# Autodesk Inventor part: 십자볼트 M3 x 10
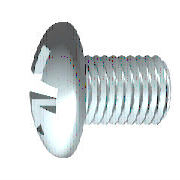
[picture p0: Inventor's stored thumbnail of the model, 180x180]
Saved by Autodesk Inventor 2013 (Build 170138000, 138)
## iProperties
IsCustomPart: 0
Created: 2012-02
Part Number: 십자볼트 M3 x 10
Material: 스테인리스강
Description: 십자 오목 머리 나사
Document SubType Name: Modeling
Standard: KS B 1023
Designer: mduedu
Standards Organization: KS
Language: ko-KR
Size Designation: A  M 3 x 10 - H
Categories: <MemberInstance><Categories><Category DisplayName="조임쇠" InternalName="e4da775c-781d-43d5-af7c-5136215cf5a6" Mnemonic="FSTN"><Category DisplayName="볼트" InternalN
Density: 1 g/cm^3
Author: mduedu
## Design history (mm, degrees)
workplane "Work Plane3"
sketch "스케치2"
  geometry: L1 (-3.72, 0)-(3.72, 0) reference; L2 (0, -3.72)-(0, 3.72) reference; L3 (0, 1.5)-(0, 0); L4 (0, 0)-(1.5, 0); L5 (0, 0)-(1.879, 1.879); L6 (0.253, 1.479)-(0.261, 0.456); L7 (1.479, 0.253)-(0.456, 0.261); L8 (0.253, -1.479)-(0.261, -0.456); L9 (1.479, -0.253)-(0.456, -0.261); L10 (-0.253, 1.479)-(-0.261, 0.456); L11 (-1.479, 0.253)-(-0.456, 0.261); L12 (-1.479, -0.253)-(-0.456, -0.261); L13 (-0.253, -1.479)-(-0.261, -0.456); A1 r 0.45 centre (0, 0) between (0.45, 0) and (0, 0.45); A2 r 1.5 centre (0, 0) between (1.5, 0) and (1.479, 0.253); A3 r 1.5 centre (0, 0) between (0.253, 1.479) and (0, 1.5); A4 r 1.5 centre (0, 0) between (1.479, 0.253) and (0.253, 1.479); A5 r 1.5 centre (0, 0) between (0, -1.5) and (0.253, -1.479); A6 r 1.5 centre (0, 0) between (0.253, -1.479) and (1.479, -0.253); A7 r 1.5 centre (0, 0) between (1.479, -0.253) and (1.5, 0); A8 r 1.5 centre (0, 0) between (-1.479, 0.253) and (-1.5, 0); A9 r 1.5 centre (0, 0) between (-0.253, 1.479) and (-1.479, 0.253); A10 r 1.5 centre (0, 0) between (0, 1.5) and (-0.253, 1.479); A11 r 1.5 centre (0, 0) between (-1.5, 0) and (-1.479, -0.253); A12 r 1.5 centre (0, 0) between (-1.479, -0.253) and (-0.253, -1.479); A13 r 1.5 centre (0, 0) between (-0.253, -1.479) and (0, -1.5); A14 r 0.525 centre (0, 0) between (0.525, 0) and (0, 0.525); A15 r 0.197 centre (0.457, 0.457) between (0.261, 0.456) and (0.456, 0.261); A16 r 0.197 centre (0.457, -0.457) between (0.456, -0.261) and (0.261, -0.456); A17 r 0.197 centre (-0.457, 0.457) between (-0.456, 0.261) and (-0.261, 0.456); A18 r 0.197 centre (-0.457, -0.457) between (-0.261, -0.456) and (-0.456, -0.261); 1 further point
  constraints: 38 point on circle, 22 end point, 19 symmetric about line, 18 centre point, 4 coincident, 3 collinear, 3 point on line, 3 tangent, 1 perpendicular, 21 other
  dimensions: "d4" = 45 deg angle of L5 L4; "d5" = 0.9 diameter of A1 (= 0.3 x SDM); "d6" = 3 diameter of A4 (= SDM); "d7" = 0.2525 distance from line of L6.start L3 (= 0.5 x SBR); "d14" = 1.05 diameter of A14 (= 0.35 x SDM)
extrude "슬롯" join sketch "스케치2" taper "d15" = 5 deg; stored distance "d54" = 10
revolve "절단부" stored, may be unused: angle "d56" = 90 deg
revolve "본체" stored, may be unused: angle "d18" = 90 deg
workplane "Work Plane1"
body "Solid1"
sketch "스케치1"
  geometry: L1 (10, 0)-(10, 1.5); L2 (10, 1.5)-(1, 1.5); L3 (3.962, 5.08)-(3.962, 5.08); L4 (-2.4, 0)-(-2.4, 2.59); L5 (-2.2, 1.4)-(-1.036, 0.82); L6 (-1.036, 0.82)-(-0.6, 0); L7 (-0.6, 0)-(10, 0); L8 (-5.105, 0)-(12.517, 0) reference; L9 (0, -1.016)-(0, 6.096) reference; L10 (-2.2, 1.4)-(-2.4, 1.5); L11 (-1.636, 2.657)-(-2.4, 2.59); L12 (-1.636, 2.657)-(0, 2.8); L13 (0, 2.8)-(0, 1.347); L14 (0, 1.347)-(0.693, 1.347); L15 (0.693, 1.347)-(1, 1.5); L16 (1, 1.5)-(0, 1.5); A1 r 5 centre (2.6, 0) between (-1.636, 2.657) and (-2.4, 0)
  constraints: 28 end point, 5 point on line, 4 collinear, 4 point on circle, 3 parallel, 2 perpendicular, 1 centre point, 1 horizontal, 1 tangent
  dimensions: "d1" = 3 diameter of L2 L7 (= GD); "d2" = 1.8 distance from line of L6.end L4 (= STI); "d11" = 3 diameter of L10.end L7 (= SDM); "d12" = 62 deg angle of L6 L7; "d13" = 26.5 deg angle of L5 L7; "d17" = 5.6 diameter of L12.end L7 (= KOD); "d19" = 5 deg angle of L12 L7 (= KEWI); "d20" = 2.4 distance between parallel lines of L4 L13 (= KOH); "d21" = 5 radius of A1 (= KR); "d23" = 2.6935 diameter of L14 L7 (= BDM); "d24" = 9 distance of L1.end L2.end (= GEL); "d25" = 0.30673 horizontal distance of L14.end L2.end (= GAL); "d28" = 10 distance between parallel lines of L1 L13 (= NLG)
fillet "모깎기1" dims "d29" = 1.2 (= RR)
fillet "모깎기2" dims "d16" = 0.101 (= 0.2 x SBR)
feature "스레드" dims "d8" = 9 (= GEL), "d9" = 0
chamfer "모따기1" distance "d26" = 0.30673 (= -0.5 x SPD + 0.5 x GD); stored, may be unused: second distance "d27" = 0.30683 (computed from GUL), angle "d78" = 45 deg
other parameters: "GD" = 3 (= NND) [user parameter; used in 2 equation terms], "NLG" = 10 [user parameter; used in 1 equation term], "GEL" = 9 [user parameter; used in 2 equation terms], "KOD" = 5.6 [user parameter; used in 1 equation term], "KOH" = 2.4 [user parameter; used in 2 equation terms], "SDM" = 3 [user parameter; used in 4 equation terms], "STI" = 1.8 [user parameter; used in 1 equation term], "SBR" = 0.505 [user parameter; used in 2 equation terms], "GAL" = 0.30673 (= 0.61345 x PTC) [user parameter; used in 1 equation term], "SPD" = 2.38655 (= NND - 1.2269 x PTC) [user parameter; used in 1 equation term], "KEWI" = 5 deg [user parameter; used in 1 equation term], "d3" = -2.4 (= -KOH), "d10" = 0, "KR" = 5 [user parameter; used in 1 equation term], "BDM" = 2.6935 [user parameter; used in 1 equation term], "GUL" = 0.30673 (= 0.61345 x PTC) [user parameter; used in 1 equation term], "RR" = 1.2 [user parameter; used in 1 equation term], "d79" = 0, "d80" = 0, "PTC" = 0.5 [user parameter; used in 5 equation terms], "THREADDIA" = 3 [user parameter; used in 1 equation term], "TOA" = 30 deg [user parameter], "NND" = 3 [user parameter; used in 2 equation terms], "GD1" = 2.38655 (= THREADDIA - 1.2269 x PTC) [user parameter]
